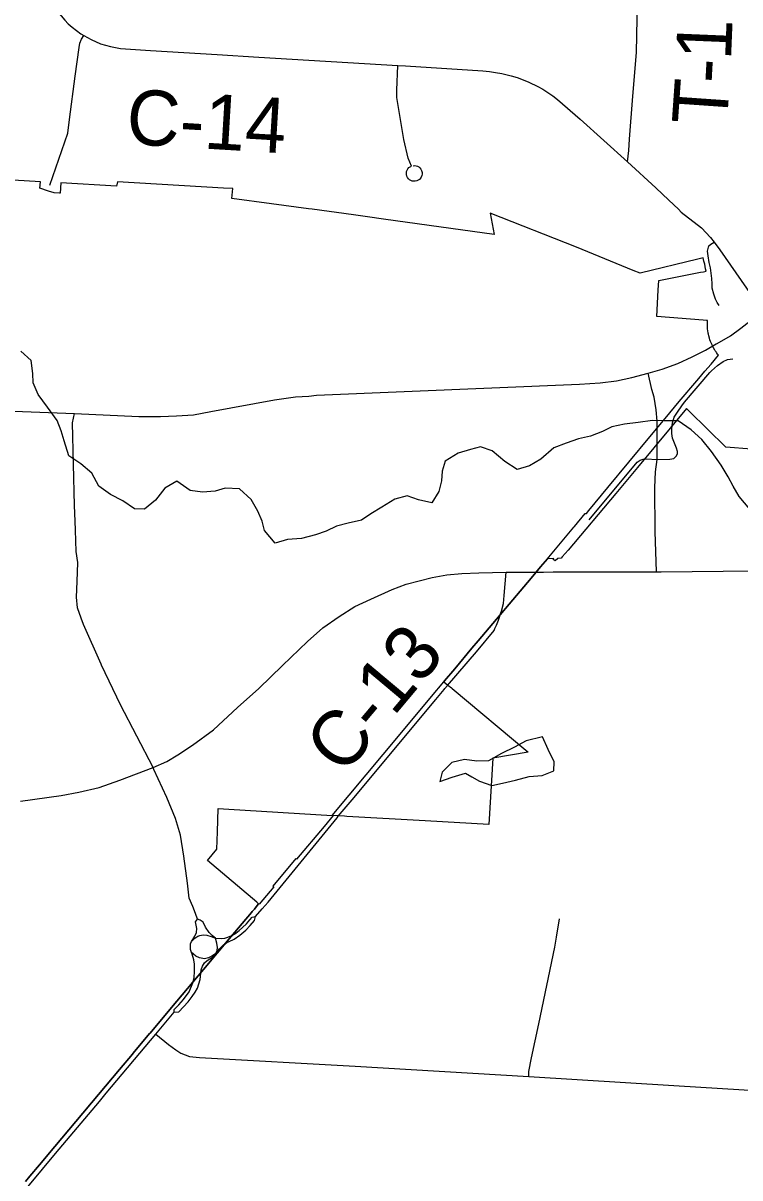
# Model space of a CAD drawing. Extents: x 0 to 34, y 0 to 22.
# Drawn here: x 6.699 to 7.438, y 7.332 to 8.523 of the extents above; entities that cross this region are included whole.
import ezdxf

# ---------------------------------------------------------------- set-up
doc = ezdxf.new("R2010")
doc.units = 0
for name, color, linetype in [('GM_X_Corporation', 7, 'Continuous'), ('GM_X_County_Road', 7, 'Continuous'), ('GM_X_County_Road_Text', 7, 'Continuous'), ('GM_X_Minor_Lake', 7, 'Continuous'), ('GM_X_Minor_River', 7, 'Continuous'), ('GM_X_Township_Road', 7, 'Continuous'), ('GM_X_Township_Road_Text', 7, 'Continuous')]:
    doc.layers.add(name, color=color, linetype=linetype)

msp = doc.modelspace()

# ---------------------------------------------------------------- linework, layer by layer
at = {"layer": 'GM_X_Corporation'}
for points in [[(6.7015, 7.3285), (6.7061, 7.334), (6.7159, 7.3456), (6.732, 7.3648), (6.7985, 7.4441), (6.8118, 7.4599), (6.8125, 7.4608), (6.8296, 7.4811), (6.83, 7.4816), (6.8522, 7.508), (6.8851, 7.5473), (6.9116, 7.5789), (6.9345, 7.6061), (6.9353, 7.6069), (6.9361, 7.6077), (6.9376, 7.6094), (6.9383, 7.6106), (6.942, 7.615), (6.9403, 7.6165), (6.8891, 7.6596), (6.899, 7.6714), (6.8995, 7.6891), (6.9002, 7.7131), (6.9114, 7.7124), (7.0179, 7.7059), (7.0879, 7.7899), (7.1202, 7.8286), (7.1329, 7.8438), (7.1336, 7.8447), (7.1442, 7.8574), (7.162, 7.8786), (7.1683, 7.886), (7.2229, 7.9508), (7.2328, 7.9625), (7.2399, 7.9708), (7.2413, 7.9725), (7.2671, 8.0032), (7.2677, 8.0039), (7.2788, 8.0175), (7.2799, 8.0175), (7.2824, 8.0205), (7.3021, 8.0441), (7.3455, 8.0965), (7.3613, 8.1155), (7.3757, 8.1328), (7.3938, 8.1543), (7.3958, 8.1565), (7.4022, 8.1641), (7.4085, 8.1715), (7.4163, 8.1806), (7.4159, 8.1811), (7.4152, 8.1819), (7.4142, 8.1833), (7.4137, 8.184), (7.4128, 8.1853), (7.4124, 8.186), (7.4111, 8.1882), (7.4103, 8.1897), (7.4097, 8.1909), (7.4095, 8.1912), (7.4086, 8.1933), (7.408, 8.1948), (7.4074, 8.1964), (7.4068, 8.1983), (7.4061, 8.2008), (7.4057, 8.2024), (7.4055, 8.2035), (7.4051, 8.206), (7.405, 8.2074), (7.4048, 8.2093), (7.4047, 8.2114), (7.4047, 8.2137), (7.4048, 8.2163), (7.4039, 8.2164), (7.4003, 8.2167), (7.3527, 8.2207), (7.3541, 8.2479), (7.3547, 8.2578), (7.3977, 8.2662), (7.4008, 8.2668), (7.4033, 8.2673), (7.4029, 8.2699), (7.402, 8.2744), (7.4012, 8.2777), (7.4003, 8.2811), (7.3948, 8.2798), (7.3353, 8.2654), (7.3282, 8.2681), (7.2696, 8.292), (7.1808, 8.3273), (7.1849, 8.3051), (7.118, 8.3143), (7.0709, 8.3209), (7.0543, 8.3233), (7.0397, 8.3254), (6.9971, 8.3312), (6.9933, 8.3317), (6.9551, 8.3367), (6.9142, 8.3423), (6.9154, 8.3525), (6.9056, 8.353), (6.7963, 8.3593), (6.7955, 8.3549), (6.738, 8.3583), (6.7375, 8.3477), (6.7365, 8.3478), (6.7311, 8.3481), (6.7252, 8.3499), (6.7164, 8.3528), (6.717, 8.3595), (6.6491, 8.3637)], [(7.4502, 8.0839), (7.4239, 8.0857), (7.4239, 8.0858), (7.386, 8.1228), (7.3831, 8.1256), (7.3328, 8.0648), (7.3104, 8.0379), (7.2611, 7.9797), (7.2551, 7.9726), (7.2539, 7.9712), (7.2505, 7.9709), (7.2476, 7.9686), (7.2458, 7.9701), (7.2465, 7.9709), (7.2399, 7.9708), (7.2328, 7.9625), (7.2229, 7.9508), (7.1683, 7.886), (7.162, 7.8786), (7.1442, 7.8574), (7.1336, 7.8447), (7.133, 7.844), (7.1329, 7.8438), (7.1372, 7.8404), (7.1408, 7.8375), (7.1415, 7.8369), (7.2196, 7.7716), (7.22, 7.7713), (7.1834, 7.765), (7.1795, 7.6966), (7.1138, 7.7005), (7.0329, 7.7051), (7.0306, 7.7053), (7.0247, 7.7056), (7.0187, 7.7059), (7.0095, 7.6948), (6.9811, 7.6609), (6.9804, 7.6615), (6.9567, 7.6332), (6.9575, 7.6325), (6.9425, 7.6146), (6.942, 7.615), (6.9383, 7.6106), (6.9376, 7.6094), (6.9361, 7.6077), (6.9353, 7.6069), (6.9345, 7.6061), (6.9116, 7.5789), (6.8851, 7.5473), (6.8522, 7.508), (6.83, 7.4816), (6.8296, 7.4811), (6.8125, 7.4608), (6.8118, 7.4599), (6.7985, 7.4441), (6.732, 7.3648), (6.7159, 7.3456), (6.7061, 7.334), (6.7015, 7.3285)]]:
    msp.add_lwpolyline(points, dxfattribs=at)
at = {"layer": 'GM_X_County_Road'}
for p, q in [((7.3748, 8.3312), (7.3778, 8.3283)), ((6.7532, 8.0004), (6.7528, 8.0095)), ((7.1971, 7.9571), (7.2267, 7.9571)), ((7.2476, 7.9572), (7.3521, 7.9573)), ((7.3521, 7.9573), (7.3571, 7.9573)), ((6.8341, 7.7535), (6.8333, 7.7554)), ((6.9389, 7.602), (6.9457, 7.6097)), ((6.7327, 7.3573), (6.7778, 7.4112))]:
    msp.add_line(p, q, dxfattribs=at)
for points in [[(6.5703, 8.6841), (6.59, 8.6755), (6.608, 8.666), (6.6308, 8.652), (6.6465, 8.6402), (6.6593, 8.6295), (6.6749, 8.6152), (6.6877, 8.6016), (6.7031, 8.5824), (6.7181, 8.5603), (6.7345, 8.5351), (6.742, 8.5262), (6.7457, 8.5225), (6.7498, 8.5189), (6.7587, 8.5122), (6.7616, 8.5104)], [(6.7616, 8.5104), (6.7694, 8.5061), (6.7791, 8.5019), (6.7841, 8.5003), (6.7892, 8.4989), (6.7943, 8.4979), (6.7995, 8.4971), (6.8306, 8.4948), (6.8993, 8.4906), (6.9421, 8.488), (7.0856, 8.4793), (7.0933, 8.4789), (7.1732, 8.474), (7.18, 8.4732), (7.1863, 8.4723), (7.1926, 8.4712), (7.2023, 8.4687), (7.2085, 8.4669), (7.2147, 8.4647), (7.2207, 8.4623), (7.2299, 8.4579), (7.2352, 8.4549), (7.2453, 8.4482), (7.2501, 8.4445), (7.2736, 8.4239), (7.3225, 8.3801), (7.3516, 8.3531), (7.3651, 8.3405), (7.3748, 8.3312)], [(7.3778, 8.3283), (7.3987, 8.3121), (7.4079, 8.3022), (7.4117, 8.2971), (7.4177, 8.2894), (7.4616, 8.2262)], [(7.4167, 8.232), (7.4147, 8.2349), (7.413, 8.2384), (7.4112, 8.2435), (7.4095, 8.2497), (7.4095, 8.2541), (7.4092, 8.2596), (7.4087, 8.2651), (7.4078, 8.2706), (7.4064, 8.2764), (7.4056, 8.2831), (7.4048, 8.2881), (7.4062, 8.2933), (7.4082, 8.2953), (7.4117, 8.2971)], [(7.4147, 8.1928), (7.4286, 8.2006), (7.4392, 8.2087), (7.453, 8.2191), (7.4616, 8.2262)], [(7.3891, 8.1791), (7.4029, 8.186), (7.4139, 8.1923), (7.4147, 8.1928)], [(7.3435, 8.1621), (7.358, 8.1661), (7.3743, 8.1722), (7.3891, 8.1791)], [(7.3681, 8.1048), (7.3686, 8.1108), (7.3706, 8.1166), (7.3738, 8.122), (7.3783, 8.1283), (7.3811, 8.1322), (7.4074, 8.1627), (7.4091, 8.1647), (7.415, 8.1701), (7.421, 8.1742), (7.4254, 8.1762), (7.4309, 8.1768)], [(6.7521, 8.1204), (6.8184, 8.1174), (6.8407, 8.1174), (6.8572, 8.118), (6.8749, 8.1193), (6.8927, 8.1226), (6.9585, 8.1345), (6.98, 8.1379), (6.9938, 8.1384), (7.0017, 8.1394), (7.273, 8.1507), (7.2942, 8.1522), (7.3109, 8.1542), (7.3267, 8.1576), (7.3435, 8.1621)], [(7.3529, 8.1069), (7.3529, 8.1126), (7.3519, 8.1244), (7.3499, 8.1375), (7.3474, 8.1454), (7.3435, 8.1621)], [(6.3612, 8.1392), (6.3873, 8.1379), (6.5227, 8.1306), (6.5924, 8.1268), (6.6047, 8.1262), (6.6262, 8.1253), (6.7521, 8.1204)], [(6.7528, 8.0095), (6.7522, 8.0257), (6.7499, 8.1109), (6.7521, 8.1204)], [(7.353, 8.0844), (7.3529, 8.0933), (7.3529, 8.1069)], [(7.3531, 8.0732), (7.3661, 8.0735), (7.37, 8.0743), (7.3724, 8.0764), (7.3738, 8.0789), (7.3738, 8.0813), (7.373, 8.0848), (7.37, 8.0918), (7.3689, 8.0951), (7.368, 8.0999), (7.3681, 8.1048)], [(7.3521, 7.9573), (7.3509, 7.9988), (7.3506, 8.0444), (7.3512, 8.0604), (7.3531, 8.0732), (7.353, 8.0844)], [(6.7796, 7.8619), (6.7615, 7.9028), (6.7591, 7.9094), (6.7553, 7.9203), (6.7543, 7.9312), (6.7548, 7.9474), (6.7556, 7.967), (6.754, 7.9781), (6.7532, 8.0004)], [(6.6966, 7.7209), (6.7383, 7.7265), (6.7565, 7.73), (6.7776, 7.735), (6.7989, 7.7423), (6.8333, 7.7554), (6.8473, 7.7616), (6.8586, 7.7684), (6.8737, 7.7784), (6.8955, 7.7945), (6.9203, 7.8173), (6.9422, 7.8369), (6.9665, 7.8607), (6.9923, 7.8856), (7.0082, 7.8994), (7.0252, 7.9112), (7.0413, 7.9215), (7.0578, 7.9292), (7.0797, 7.939), (7.0942, 7.9445), (7.1208, 7.9516), (7.1361, 7.9541), (7.1514, 7.9556), (7.169, 7.9563), (7.1971, 7.9571)], [(7.1924, 7.9168), (7.1945, 7.9246), (7.1953, 7.933), (7.1971, 7.9571)], [(7.2267, 7.9571), (7.2356, 7.9571), (7.2457, 7.9572)], [(7.2457, 7.9572), (7.2467, 7.9572), (7.2476, 7.9572)], [(7.3571, 7.9573), (7.4849, 7.9586), (7.5968, 7.9606), (7.6716, 7.9606), (7.7217, 7.9606), (7.7724, 7.9586), (7.8622, 7.9563), (7.8672, 7.9559)], [(7.1852, 7.8978), (7.1856, 7.8987), (7.1871, 7.9023), (7.1892, 7.9073), (7.1922, 7.9159), (7.1924, 7.9168)], [(7.1334, 7.836), (7.1341, 7.8368), (7.1367, 7.8399), (7.1665, 7.8749), (7.1848, 7.8969), (7.1852, 7.8978)], [(6.8333, 7.7554), (6.7995, 7.8202), (6.78, 7.861), (6.7796, 7.8619)], [(7.0229, 7.7037), (7.0241, 7.7053), (7.0383, 7.7222), (7.1248, 7.8257), (7.1334, 7.836)], [(6.8705, 7.6207), (6.8685, 7.6361), (6.865, 7.664), (6.8613, 7.6856), (6.8562, 7.7028), (6.8474, 7.7247), (6.8341, 7.7535)], [(6.9457, 7.6097), (6.9518, 7.6167), (7.0229, 7.7037)], [(6.8788, 7.5991), (6.877, 7.6051), (6.874, 7.6123), (6.8705, 7.6207)], [(6.8726, 7.5762), (6.874, 7.5783), (6.8761, 7.5816), (6.8778, 7.5854), (6.8784, 7.5896), (6.877, 7.5964), (6.8788, 7.5991)], [(6.8974, 7.5795), (6.8942, 7.5824), (6.8911, 7.5854), (6.8873, 7.5909), (6.8847, 7.596), (6.8816, 7.5981), (6.8788, 7.5991)], [(6.8974, 7.5795), (6.9034, 7.5793), (6.9071, 7.5796), (6.9103, 7.5804), (6.9144, 7.5823), (6.9184, 7.5848), (6.9219, 7.5873), (6.9255, 7.5904), (6.9294, 7.5944), (6.9329, 7.5985), (6.9352, 7.6011), (6.9389, 7.602)], [(6.8975, 7.5635), (6.9016, 7.5686), (6.9059, 7.5727), (6.9093, 7.575), (6.9117, 7.5762), (6.9166, 7.5786), (6.9226, 7.5826), (6.9287, 7.5879), (6.9334, 7.5926), (6.9378, 7.5977), (6.9389, 7.602)], [(6.8729, 7.5648), (6.8718, 7.5678), (6.8716, 7.5735), (6.8726, 7.5762)], [(6.8726, 7.5762), (6.8762, 7.5795), (6.8792, 7.5816), (6.8815, 7.5824), (6.8849, 7.583), (6.8886, 7.5827), (6.8929, 7.5813), (6.8974, 7.5795)], [(6.8975, 7.5635), (6.8991, 7.5668), (6.8996, 7.5698), (6.8989, 7.5745), (6.8974, 7.5795)], [(6.855, 7.5032), (6.855, 7.506), (6.8596, 7.5107), (6.8646, 7.5164), (6.8704, 7.524), (6.8742, 7.5334), (6.8754, 7.5385), (6.8757, 7.5456), (6.8758, 7.5526), (6.8751, 7.5572), (6.8736, 7.563), (6.8729, 7.5648)], [(6.855, 7.5032), (6.8596, 7.5037), (6.8693, 7.514), (6.8736, 7.5195), (6.8767, 7.5239), (6.8791, 7.5281), (6.8805, 7.5323), (6.8816, 7.537), (6.8823, 7.5434), (6.8828, 7.5468), (6.8842, 7.5506), (6.8863, 7.5539), (6.8889, 7.5566), (6.8918, 7.5582), (6.8948, 7.5603), (6.8975, 7.5635)], [(6.8975, 7.5635), (6.8939, 7.5609), (6.8902, 7.5592), (6.8862, 7.5582), (6.8809, 7.5591), (6.8772, 7.561), (6.8749, 7.5629), (6.8729, 7.5648)], [(6.7778, 7.4112), (6.7849, 7.4197), (6.8359, 7.4804), (6.855, 7.5032)], [(6.6094, 7.2119), (6.6199, 7.2225), (6.653, 7.2605), (6.7056, 7.325), (6.7327, 7.3573)]]:
    msp.add_lwpolyline(points, dxfattribs=at)
at = {"layer": 'GM_X_Minor_Lake'}
for points in [[(7.2347, 7.7871), (7.218, 7.7829), (7.2059, 7.7765), (7.1923, 7.77), (7.1791, 7.7624), (7.167, 7.762), (7.1541, 7.7639), (7.1413, 7.7608), (7.1311, 7.7506), (7.1288, 7.7411), (7.1417, 7.7457), (7.1553, 7.7495), (7.162, 7.7458)], [(7.162, 7.7458), (7.1697, 7.7415), (7.1825, 7.737), (7.1935, 7.7393), (7.2067, 7.7423), (7.2211, 7.7462), (7.2344, 7.7473), (7.2465, 7.7519), (7.2468, 7.7614), (7.2404, 7.7742), (7.2347, 7.7871)]]:
    msp.add_lwpolyline(points, dxfattribs=at)
at = {"layer": 'GM_X_Minor_River'}
for points in [[(6.7148, 8.1401), (6.7095, 8.1522), (6.7091, 8.1617), (6.7075, 8.1753), (6.6969, 8.1848)], [(7.4486, 8.0218), (7.4376, 8.035), (7.4312, 8.0456), (7.4262, 8.0551), (7.419, 8.0672), (7.4088, 8.0812), (7.399, 8.0937), (7.388, 8.1036), (7.3747, 8.113), (7.36, 8.113), (7.3482, 8.1134), (7.3335, 8.1114), (7.3191, 8.1095), (7.3062, 8.1069), (7.2964, 8.1019), (7.2843, 8.0973), (7.2718, 8.0943), (7.259, 8.0901), (7.2465, 8.0852), (7.2329, 8.0734), (7.2212, 8.0665), (7.2087, 8.0627), (7.1958, 8.071), (7.1829, 8.082), (7.1708, 8.0862), (7.1606, 8.0835), (7.1477, 8.0797), (7.1345, 8.0713), (7.1311, 8.0611), (7.1304, 8.0512), (7.1277, 8.0402), (7.1205, 8.0285), (7.1069, 8.0315), (7.0952, 8.0356), (7.0823, 8.0322), (7.0691, 8.0238), (7.0577, 8.017), (7.0479, 8.0105), (7.0343, 8.0075), (7.0222, 8.0044), (7.0116, 7.9991), (7.0006, 7.9953), (6.9862, 7.9915), (6.9719, 7.9907), (6.959, 7.9869), (6.948, 7.9998), (6.9457, 8.0096), (6.9412, 8.0198), (6.9344, 8.032), (6.9222, 8.0429), (6.9075, 8.0437), (6.8973, 8.0406), (6.884, 8.0395), (6.8715, 8.041), (6.8575, 8.0508), (6.8454, 8.0436), (6.8356, 8.0311), (6.8243, 8.0219), (6.814, 8.0223), (6.8019, 8.0306), (6.7894, 8.037), (6.7773, 8.0457), (6.7701, 8.059), (6.7587, 8.0685), (6.7463, 8.0768), (6.7413, 8.0923), (6.7383, 8.1026), (6.7341, 8.1132), (6.7243, 8.1272), (6.7148, 8.1401)]]:
    msp.add_lwpolyline(points, dxfattribs=at)
at = {"layer": 'GM_X_Township_Road'}
msp.add_line((7.2491, 7.5805), (7.2524, 7.5994), dxfattribs=at)
for points in [[(7.3225, 8.3801), (7.3238, 8.3918), (7.3244, 8.4034), (7.3277, 8.4477), (7.3317, 8.4929), (7.3345, 8.6341)], [(6.7266, 8.3561), (6.7451, 8.4096), (6.7471, 8.4236), (6.7529, 8.4684), (6.7568, 8.4981), (6.7577, 8.5026), (6.7593, 8.5066), (6.7616, 8.5104)], [(7.1012, 8.376), (7.1027, 8.3762), (7.1043, 8.376), (7.1058, 8.3755), (7.1071, 8.3748), (7.1083, 8.3738), (7.1093, 8.3725), (7.11, 8.3712), (7.1105, 8.369), (7.1105, 8.3674), (7.1102, 8.3659), (7.1096, 8.3644), (7.1088, 8.3631), (7.1077, 8.3619), (7.1064, 8.361), (7.105, 8.3604), (7.1035, 8.36), (7.1019, 8.36), (7.1003, 8.3602), (7.0989, 8.3608), (7.0975, 8.3616), (7.0964, 8.3626), (7.0954, 8.3639), (7.0948, 8.3653), (7.0944, 8.3669), (7.0943, 8.3685), (7.0946, 8.3701), (7.0951, 8.3716), (7.096, 8.373), (7.0969, 8.3741), (7.0997, 8.3756), (7.0961, 8.3839), (7.0918, 8.403), (7.0844, 8.4463), (7.0845, 8.4541), (7.0856, 8.4793)], [(7.2827, 8.011), (7.3323, 8.0703), (7.3354, 8.0723), (7.3384, 8.0735), (7.3415, 8.0739), (7.3531, 8.0732)], [(7.2205, 7.437), (7.2206, 7.4421), (7.2233, 7.4561), (7.2309, 7.4912), (7.2473, 7.5701), (7.2491, 7.5805)], [(6.8359, 7.4804), (6.849, 7.4697), (6.8565, 7.4642), (6.8617, 7.4608), (6.8707, 7.4576), (6.881, 7.4564), (7.0414, 7.4476), (7.2205, 7.437), (7.3702, 7.4276), (7.4651, 7.4217), (7.4766, 7.4212), (7.4941, 7.4201), (7.5076, 7.4187)]]:
    msp.add_lwpolyline(points, dxfattribs=at)

# ---------------------------------------------------------------- texts
at = {"layer": 'GM_X_County_Road_Text'}
for s, rotation, p in [('C-14', 356.5731, (6.8046, 8.3986)), ('C-13', 49.99, (7.0295, 7.7459))]:
    msp.add_text(s, height=0.05682, rotation=rotation, dxfattribs=at).set_placement(p)
at = {"layer": 'GM_X_Township_Road_Text'}
for s, rotation, p in [('1', 87.6171, (7.429, 8.4842)), ('-', 86.8736, (7.4277, 8.4601)), ('T', 86.0197, (7.4247, 8.4168))]:
    msp.add_text(s, height=0.0568, rotation=rotation, dxfattribs=at).set_placement(p)

doc.saveas('drawing.dxf')
